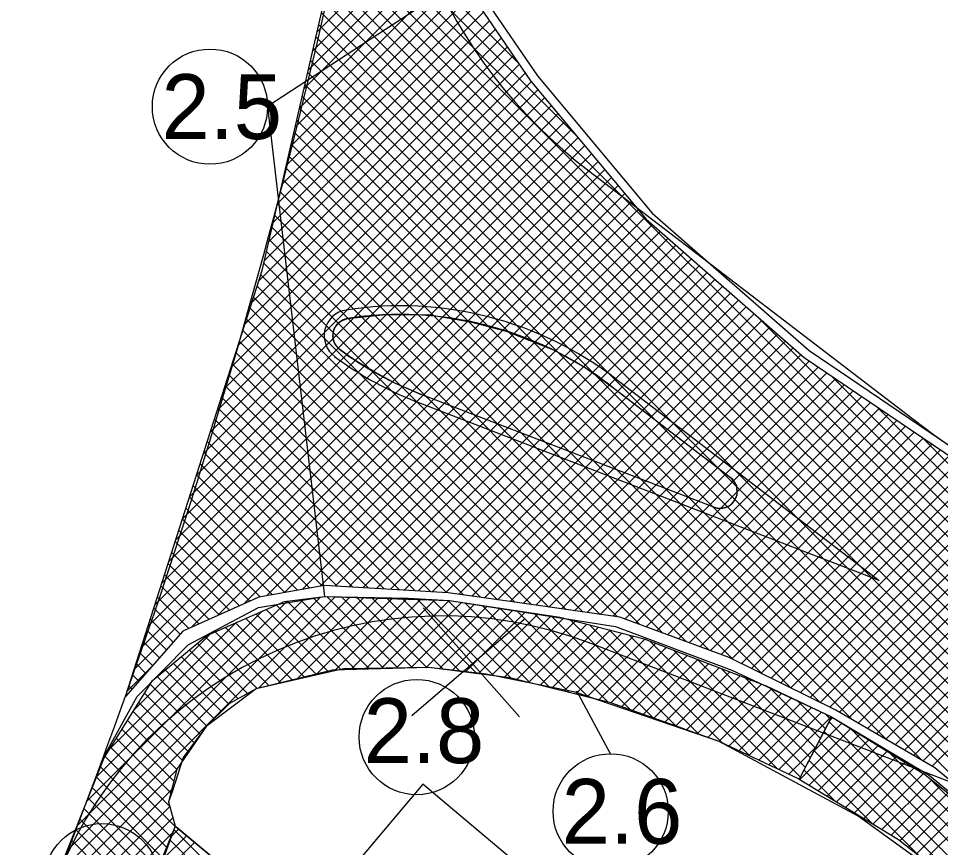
# Model space of a CAD drawing. Extents: x -438410 to -437811, y -1133174 to -1132817.
# Drawn here: x -438157.89 to -438131.22, y -1132954.3 to -1132930.32 of the extents above; entities that cross this region are included whole.
import ezdxf

# ---------------------------------------------------------------- set-up
doc = ezdxf.new("R2010")
doc.units = 0
for name, color, linetype in [('10 - legenda', 7, 'Continuous'), ('Vrstva 1', 7, 'Continuous'), ('Vrstva 5', 7, 'Continuous')]:
    doc.layers.add(name, color=color, linetype=linetype)

msp = doc.modelspace()

# ---------------------------------------------------------------- linework, layer by layer
at = {"layer": '10 - legenda'}
for p, q in [((-438148.336, -1132926.71), (-438143.442, -1132931.604)), ((-438148.415, -1132927.055), (-438141.759, -1132933.71)), ((-438149.256, -1132930.707), (-438145.83, -1132927.282)), ((-438148.495, -1132927.399), (-438113.459, -1132962.435)), ((-438149.383, -1132931.258), (-438145.694, -1132927.57)), ((-438148.574, -1132927.744), (-438113.683, -1132962.635)), ((-438149.509, -1132931.809), (-438145.558, -1132927.858)), ((-438149.636, -1132932.36), (-438145.422, -1132928.146)), ((-438148.653, -1132928.089), (-438113.907, -1132962.835)), ((-438149.763, -1132932.911), (-438145.286, -1132928.434)), ((-438148.733, -1132928.434), (-438114.132, -1132963.035)), ((-438149.89, -1132933.462), (-438145.15, -1132928.722)), ((-438148.812, -1132928.779), (-438114.356, -1132963.235)), ((-438150.017, -1132934.014), (-438145.014, -1132929.011)), ((-438150.143, -1132934.565), (-438144.878, -1132929.299)), ((-438148.891, -1132929.124), (-438114.58, -1132963.435)), ((-438150.27, -1132935.116), (-438144.741, -1132929.587)), ((-438148.971, -1132929.469), (-438114.805, -1132963.635)), ((-438150.397, -1132935.667), (-438144.605, -1132929.875)), ((-438149.05, -1132929.814), (-438115.029, -1132963.835)), ((-438150.524, -1132936.218), (-438144.447, -1132930.141)), ((-438150.651, -1132936.769), (-438144.274, -1132930.392)), ((-438149.129, -1132930.159), (-438115.253, -1132964.035)), ((-438150.778, -1132937.32), (-438144.101, -1132930.644)), ((-438149.209, -1132930.503), (-438115.478, -1132964.235)), ((-438150.94, -1132937.907), (-438143.928, -1132930.895)), ((-438149.288, -1132930.848), (-438115.702, -1132964.435)), ((-438151.14, -1132938.531), (-438143.756, -1132931.147)), ((-438149.368, -1132931.193), (-438115.926, -1132964.634)), ((-438151.341, -1132939.156), (-438143.583, -1132931.398)), ((-438151.541, -1132939.781), (-438143.41, -1132931.65)), ((-438149.447, -1132931.538), (-438116.151, -1132964.834)), ((-438151.742, -1132940.405), (-438143.237, -1132931.901)), ((-438149.526, -1132931.883), (-438116.375, -1132965.034)), ((-438151.942, -1132941.03), (-438143.063, -1132932.151)), ((-438149.606, -1132932.228), (-438116.599, -1132965.234)), ((-438152.142, -1132941.655), (-438142.87, -1132932.382)), ((-438152.343, -1132942.279), (-438142.676, -1132932.613)), ((-438149.685, -1132932.573), (-438116.824, -1132965.434)), ((-438152.744, -1132943.529), (-438142.29, -1132933.075)), ((-438152.543, -1132942.904), (-438142.483, -1132932.844)), ((-438149.764, -1132932.918), (-438117.048, -1132965.634)), ((-438152.944, -1132944.153), (-438142.097, -1132933.306)), ((-438149.844, -1132933.263), (-438129.751, -1132953.356)), ((-438153.144, -1132944.778), (-438141.904, -1132933.537)), ((-438149.923, -1132933.608), (-438131.752, -1132951.778)), ((-438153.345, -1132945.403), (-438141.711, -1132933.769)), ((-438153.545, -1132946.027), (-438141.518, -1132934)), ((-438150.003, -1132933.952), (-438132.768, -1132951.187)), ((-438153.746, -1132946.652), (-438141.324, -1132934.231)), ((-438150.082, -1132934.297), (-438133.783, -1132950.596)), ((-438153.946, -1132947.277), (-438141.131, -1132934.462)), ((-438150.161, -1132934.642), (-438134.704, -1132950.1)), ((-438154.347, -1132948.526), (-438140.745, -1132934.924)), ((-438154.147, -1132947.901), (-438140.938, -1132934.693)), ((-438154.547, -1132949.151), (-438140.552, -1132935.155)), ((-438150.241, -1132934.987), (-438135.542, -1132949.686)), ((-438152.903, -1132947.931), (-438140.359, -1132935.386)), ((-438150.32, -1132935.332), (-438136.38, -1132949.272)), ((-438152.139, -1132947.591), (-438140.166, -1132935.618)), ((-438150.399, -1132935.677), (-438137.218, -1132948.858)), ((-438151.375, -1132947.251), (-438139.972, -1132935.849)), ((-438150.479, -1132936.022), (-438137.912, -1132948.589)), ((-438150.717, -1132947.017), (-438139.779, -1132936.08)), ((-438150.2, -1132946.925), (-438139.56, -1132936.284)), ((-438150.558, -1132936.367), (-438138.583, -1132948.342)), ((-438149.683, -1132946.832), (-438139.333, -1132936.482)), ((-438150.638, -1132936.712), (-438139.253, -1132948.096)), ((-438149.167, -1132946.74), (-438139.107, -1132936.681)), ((-438150.717, -1132937.056), (-438139.924, -1132947.85)), ((-438148.738, -1132946.735), (-438138.881, -1132936.879)), ((-438148.337, -1132946.759), (-438138.655, -1132937.077)), ((-438147.936, -1132946.782), (-438138.429, -1132937.275)), ((-438150.796, -1132937.401), (-438140.57, -1132947.628)), ((-438147.535, -1132946.806), (-438138.202, -1132937.473)), ((-438150.885, -1132937.736), (-438141.065, -1132947.557)), ((-438147.135, -1132946.829), (-438137.976, -1132937.671)), ((-438146.734, -1132946.853), (-438137.75, -1132937.869)), ((-438150.988, -1132938.058), (-438141.56, -1132947.486)), ((-438146.333, -1132946.876), (-438137.524, -1132938.067)), ((-438151.092, -1132938.379), (-438142.055, -1132947.415)), ((-438145.932, -1132946.9), (-438137.298, -1132938.265)), ((-438145.531, -1132946.923), (-438137.071, -1132938.463)), ((-438145.155, -1132946.971), (-438136.845, -1132938.661)), ((-438151.195, -1132938.7), (-438142.55, -1132947.344)), ((-438144.784, -1132947.025), (-438136.619, -1132938.859)), ((-438136.551, -1132938.919), (-438113.234, -1132962.235)), ((-438151.298, -1132939.021), (-438143.045, -1132947.274)), ((-438144.413, -1132947.078), (-438136.393, -1132939.057)), ((-438151.401, -1132939.343), (-438143.541, -1132947.203)), ((-438144.042, -1132947.131), (-438136.167, -1132939.255)), ((-438143.671, -1132947.184), (-438135.94, -1132939.453)), ((-438151.504, -1132939.664), (-438144.036, -1132947.132)), ((-438143.3, -1132947.237), (-438135.714, -1132939.651)), ((-438151.607, -1132939.985), (-438144.531, -1132947.061)), ((-438142.929, -1132947.29), (-438135.488, -1132939.85)), ((-438142.558, -1132947.343), (-438135.262, -1132940.048)), ((-438142.186, -1132947.397), (-438135.019, -1132940.229)), ((-438151.71, -1132940.306), (-438145.026, -1132946.99)), ((-438141.815, -1132947.45), (-438134.766, -1132940.401)), ((-438151.813, -1132940.627), (-438145.516, -1132946.924)), ((-438141.444, -1132947.503), (-438134.513, -1132940.572)), ((-438141.073, -1132947.556), (-438134.261, -1132940.743)), ((-438134.389, -1132940.656), (-438113.01, -1132962.035)), ((-438151.916, -1132940.949), (-438145.967, -1132946.898)), ((-438140.702, -1132947.609), (-438134.008, -1132940.915)), ((-438140.359, -1132947.69), (-438133.755, -1132941.086)), ((-438152.019, -1132941.27), (-438146.418, -1132946.871)), ((-438140.048, -1132947.804), (-438133.502, -1132941.257)), ((-438152.122, -1132941.591), (-438146.868, -1132946.845)), ((-438139.738, -1132947.918), (-438133.249, -1132941.429)), ((-438139.428, -1132948.032), (-438132.996, -1132941.6)), ((-438133.074, -1132941.547), (-438112.786, -1132961.835)), ((-438139.117, -1132948.146), (-438132.743, -1132941.771)), ((-438152.225, -1132941.912), (-438147.319, -1132946.818)), ((-438138.807, -1132948.26), (-438132.49, -1132941.943)), ((-438138.497, -1132948.374), (-438132.237, -1132942.114)), ((-438152.328, -1132942.233), (-438147.77, -1132946.792)), ((-438138.187, -1132948.488), (-438131.984, -1132942.285)), ((-438152.431, -1132942.555), (-438148.22, -1132946.766)), ((-438137.876, -1132948.602), (-438131.731, -1132942.457)), ((-438137.566, -1132948.716), (-438131.478, -1132942.628)), ((-438131.759, -1132942.437), (-438112.561, -1132961.636)), ((-438152.534, -1132942.876), (-438148.671, -1132946.739)), ((-438137.262, -1132948.836), (-438131.225, -1132942.799)), ((-438152.637, -1132943.197), (-438149.105, -1132946.729)), ((-438136.978, -1132948.977), (-438130.972, -1132942.971)), ((-438136.694, -1132949.117), (-438130.707, -1132943.13)), ((-438136.41, -1132949.257), (-438130.42, -1132943.267)), ((-438136.126, -1132949.397), (-438130.133, -1132943.404)), ((-438152.74, -1132943.518), (-438149.465, -1132946.793)), ((-438135.842, -1132949.538), (-438129.846, -1132943.542)), ((-438135.558, -1132949.678), (-438129.56, -1132943.679)), ((-438152.843, -1132943.84), (-438149.825, -1132946.858)), ((-438135.274, -1132949.818), (-438129.273, -1132943.817)), ((-438134.99, -1132949.958), (-438128.986, -1132943.954)), ((-438152.946, -1132944.161), (-438150.185, -1132946.922)), ((-438134.706, -1132950.099), (-438128.699, -1132944.092)), ((-438134.422, -1132950.239), (-438128.412, -1132944.229)), ((-438153.049, -1132944.482), (-438150.545, -1132946.986)), ((-438134.145, -1132950.386), (-438128.126, -1132944.366)), ((-438133.876, -1132950.542), (-438127.839, -1132944.504)), ((-438153.153, -1132944.803), (-438150.905, -1132947.051)), ((-438133.608, -1132950.698), (-438127.552, -1132944.641)), ((-438133.34, -1132950.854), (-438127.265, -1132944.779)), ((-438133.072, -1132951.01), (-438126.978, -1132944.916)), ((-438132.804, -1132951.166), (-438126.691, -1132945.054)), ((-438153.256, -1132945.124), (-438151.205, -1132947.175)), ((-438132.536, -1132951.322), (-438126.405, -1132945.191)), ((-438132.268, -1132951.478), (-438126.096, -1132945.306)), ((-438153.359, -1132945.446), (-438151.498, -1132947.306)), ((-438131.999, -1132951.634), (-438125.774, -1132945.409)), ((-438131.731, -1132951.791), (-438125.452, -1132945.511)), ((-438131.463, -1132951.947), (-438125.13, -1132945.614)), ((-438153.462, -1132945.767), (-438151.792, -1132947.437)), ((-438153.565, -1132946.088), (-438152.085, -1132947.567)), ((-438153.668, -1132946.409), (-438152.379, -1132947.698)), ((-438153.771, -1132946.73), (-438152.673, -1132947.828)), ((-438156.76, -1132955.077), (-438148.729, -1132947.046)), ((-438156.479, -1132954.372), (-438149.161, -1132947.054)), ((-438156.197, -1132953.666), (-438149.642, -1132947.111)), ((-438155.916, -1132952.96), (-438150.124, -1132947.168)), ((-438153.874, -1132947.052), (-438152.966, -1132947.959)), ((-438150.947, -1132949.688), (-438148.312, -1132947.053)), ((-438150.398, -1132949.563), (-438147.895, -1132947.061)), ((-438150.125, -1132947.168), (-438148.167, -1132949.126)), ((-438149.848, -1132949.438), (-438147.479, -1132947.068)), ((-438149.746, -1132947.123), (-438147.749, -1132949.12)), ((-438149.366, -1132947.078), (-438147.331, -1132949.114)), ((-438149.299, -1132949.313), (-438147.062, -1132947.076)), ((-438148.979, -1132947.041), (-438146.913, -1132949.108)), ((-438148.75, -1132949.188), (-438146.645, -1132947.083)), ((-438148.547, -1132947.049), (-438146.494, -1132949.102)), ((-438148.265, -1132949.127), (-438146.243, -1132947.105)), ((-438148.115, -1132947.057), (-438146.076, -1132949.096)), ((-438147.834, -1132949.121), (-438145.841, -1132947.128)), ((-438147.683, -1132947.065), (-438145.6, -1132949.148)), ((-438147.404, -1132949.115), (-438145.44, -1132947.151)), ((-438147.251, -1132947.072), (-438145.115, -1132949.208)), ((-438146.973, -1132949.109), (-438145.07, -1132947.205)), ((-438146.819, -1132947.08), (-438144.63, -1132949.269)), ((-438146.377, -1132947.098), (-438144.145, -1132949.329)), ((-438145.927, -1132947.123), (-438143.657, -1132949.393)), ((-438145.477, -1132947.149), (-438143.093, -1132949.533)), ((-438144.984, -1132947.218), (-438142.529, -1132949.673)), ((-438155.635, -1132952.254), (-438150.833, -1132947.453)), ((-438153.977, -1132947.373), (-438153.22, -1132948.13)), ((-438150.733, -1132947.409), (-438148.916, -1132949.226)), ((-438150.438, -1132947.28), (-438148.57, -1132949.147)), ((-438146.543, -1132949.102), (-438144.701, -1132947.261)), ((-438146.185, -1132947.368), (-438143.406, -1132950.519)), ((-438146.113, -1132949.096), (-438144.333, -1132947.316)), ((-438145.724, -1132949.132), (-438143.964, -1132947.372)), ((-438145.347, -1132949.179), (-438143.595, -1132947.428)), ((-438144.97, -1132949.226), (-438143.227, -1132947.483)), ((-438144.484, -1132947.294), (-438141.964, -1132949.813)), ((-438143.984, -1132947.369), (-438141.4, -1132949.953)), ((-438143.485, -1132947.444), (-438140.836, -1132950.093)), ((-438154.08, -1132947.694), (-438153.418, -1132948.356)), ((-438151.323, -1132947.667), (-438149.607, -1132949.383)), ((-438151.028, -1132947.538), (-438149.261, -1132949.304)), ((-438146.513, -1132950.474), (-438143.271, -1132947.694)), ((-438144.593, -1132949.274), (-438142.858, -1132947.539)), ((-438144.216, -1132949.321), (-438142.489, -1132947.594)), ((-438143.838, -1132949.368), (-438142.13, -1132947.659)), ((-438143.483, -1132949.437), (-438141.793, -1132947.747)), ((-438142.985, -1132947.52), (-438140.188, -1132950.317)), ((-438142.486, -1132947.595), (-438139.527, -1132950.554)), ((-438141.95, -1132947.706), (-438138.866, -1132950.79)), ((-438155.258, -1132951.454), (-438151.588, -1132947.783)), ((-438154.183, -1132948.015), (-438153.616, -1132948.582)), ((-438151.913, -1132947.926), (-438150.298, -1132949.541)), ((-438151.618, -1132947.796), (-438149.953, -1132949.462)), ((-438143.143, -1132949.521), (-438141.457, -1132947.834)), ((-438142.803, -1132949.605), (-438141.12, -1132947.922)), ((-438142.463, -1132949.69), (-438140.783, -1132948.009)), ((-438141.377, -1132947.855), (-438138.205, -1132951.027)), ((-438140.804, -1132948.004), (-438137.526, -1132951.282)), ((-438154.545, -1132950.317), (-438152.342, -1132948.113)), ((-438152.491, -1132948.196), (-438150.989, -1132949.698)), ((-438152.208, -1132948.055), (-438150.644, -1132949.619)), ((-438142.123, -1132949.774), (-438140.446, -1132948.097)), ((-438141.783, -1132949.858), (-438140.109, -1132948.184)), ((-438141.443, -1132949.943), (-438139.775, -1132948.274)), ((-438140.231, -1132948.153), (-438136.728, -1132951.655)), ((-438154.286, -1132948.336), (-438153.815, -1132948.808)), ((-438152.722, -1132948.389), (-438151.268, -1132949.844)), ((-438141.103, -1132950.027), (-438139.468, -1132948.392)), ((-438140.764, -1132950.111), (-438139.162, -1132948.51)), ((-438139.629, -1132948.33), (-438135.93, -1132952.029)), ((-438154.389, -1132948.658), (-438154.013, -1132949.034)), ((-438153.184, -1132948.776), (-438151.809, -1132950.151)), ((-438152.953, -1132948.582), (-438151.54, -1132949.995)), ((-438140.451, -1132950.223), (-438138.855, -1132948.628)), ((-438140.138, -1132950.335), (-438138.549, -1132948.745)), ((-438138.94, -1132948.595), (-438135.282, -1132952.253)), ((-438154.748, -1132949.775), (-438154.056, -1132949.084)), ((-438154.492, -1132948.979), (-438154.211, -1132949.26)), ((-438153.415, -1132948.969), (-438152.021, -1132950.363)), ((-438139.826, -1132950.446), (-438138.243, -1132948.863)), ((-438139.514, -1132950.558), (-438137.936, -1132948.981)), ((-438138.251, -1132948.86), (-438135.137, -1132951.974)), ((-438154.595, -1132949.3), (-438154.409, -1132949.486)), ((-438153.878, -1132949.355), (-438152.446, -1132950.786)), ((-438153.647, -1132949.162), (-438152.234, -1132950.575)), ((-438139.201, -1132950.67), (-438137.63, -1132949.099)), ((-438138.889, -1132950.782), (-438137.323, -1132949.216)), ((-438138.576, -1132950.894), (-438137.017, -1132949.334)), ((-438137.562, -1132949.125), (-438134.992, -1132951.694)), ((-438154.698, -1132949.621), (-438154.607, -1132949.713)), ((-438154.081, -1132949.576), (-438152.623, -1132951.034)), ((-438138.264, -1132951.006), (-438136.71, -1132949.452)), ((-438137.952, -1132951.118), (-438136.404, -1132949.57)), ((-438136.873, -1132949.389), (-438134.847, -1132951.415)), ((-438154.244, -1132949.837), (-438152.796, -1132951.285)), ((-438137.639, -1132951.23), (-438136.107, -1132949.698)), ((-438137.35, -1132951.364), (-438135.819, -1132949.834)), ((-438136.169, -1132949.669), (-438134.702, -1132951.135)), ((-438154.408, -1132950.098), (-438152.97, -1132951.536)), ((-438137.061, -1132951.5), (-438135.532, -1132949.97)), ((-438136.772, -1132951.635), (-438135.244, -1132950.107)), ((-438135.364, -1132950.05), (-438134.558, -1132950.856)), ((-438154.571, -1132950.358), (-438153.144, -1132951.786)), ((-438136.483, -1132951.77), (-438134.956, -1132950.243)), ((-438136.194, -1132951.906), (-438134.668, -1132950.379)), ((-438154.735, -1132950.619), (-438153.315, -1132952.039)), ((-438135.905, -1132952.041), (-438134.383, -1132950.519)), ((-438134.558, -1132950.431), (-438134.413, -1132950.577)), ((-438134.449, -1132950.659), (-438120.721, -1132964.387)), ((-438134.429, -1132950.62), (-438134.352, -1132950.543)), ((-438154.898, -1132950.88), (-438153.401, -1132952.377)), ((-438135.291, -1132952.332), (-438133.828, -1132950.868)), ((-438134.892, -1132951.508), (-438134.09, -1132950.706)), ((-438134.594, -1132950.937), (-438120.304, -1132965.228)), ((-438133.795, -1132950.888), (-438121.138, -1132963.545)), ((-438155.062, -1132951.141), (-438153.487, -1132952.715)), ((-438135.028, -1132952.492), (-438133.566, -1132951.03)), ((-438134.764, -1132952.653), (-438133.304, -1132951.192)), ((-438134.74, -1132951.216), (-438119.886, -1132966.07)), ((-438155.225, -1132951.401), (-438153.516, -1132953.111)), ((-438135.616, -1132952.176), (-438134.839, -1132951.399)), ((-438134.5, -1132952.814), (-438133.041, -1132951.355)), ((-438155.389, -1132951.662), (-438153.364, -1132953.687)), ((-438134.885, -1132951.495), (-438131.82, -1132954.56)), ((-438134.237, -1132952.974), (-438132.779, -1132951.517)), ((-438133.973, -1132953.135), (-438132.517, -1132951.679)), ((-438132.681, -1132951.578), (-438121.555, -1132962.704)), ((-438155.517, -1132951.959), (-438153.487, -1132953.989)), ((-438135.031, -1132951.774), (-438133.195, -1132953.609)), ((-438133.71, -1132953.296), (-438132.255, -1132951.841)), ((-438133.446, -1132953.456), (-438131.993, -1132952.003)), ((-438157.042, -1132955.783), (-438153.321, -1132952.062)), ((-438155.638, -1132952.262), (-438153.61, -1132954.29)), ((-438135.327, -1132952.312), (-438135.295, -1132952.28)), ((-438135.176, -1132952.052), (-438134.282, -1132952.947)), ((-438133.183, -1132953.617), (-438131.731, -1132952.166)), ((-438132.919, -1132953.778), (-438131.49, -1132952.349)), ((-438132.655, -1132953.938), (-438131.254, -1132952.537)), ((-438131.471, -1132952.364), (-438122.863, -1132960.971)), ((-438157.323, -1132956.489), (-438153.466, -1132952.631)), ((-438155.759, -1132952.565), (-438153.732, -1132954.591)), ((-438132.397, -1132954.104), (-438131.017, -1132952.724)), ((-438155.88, -1132952.869), (-438153.855, -1132954.893)), ((-438132.16, -1132954.291), (-438130.781, -1132952.912)), ((-438157.605, -1132957.194), (-438153.517, -1132953.107)), ((-438156, -1132953.172), (-438153.978, -1132955.194)), ((-438131.923, -1132954.479), (-438130.544, -1132953.1)), ((-438131.686, -1132954.666), (-438130.308, -1132953.288)), ((-438157.886, -1132957.9), (-438153.427, -1132953.441)), ((-438156.121, -1132953.475), (-438154.101, -1132955.496)), ((-438157.605, -1132958.043), (-438153.443, -1132953.881)), ((-438156.242, -1132953.779), (-438154.224, -1132955.797)), ((-438153.461, -1132953.955), (-438153.268, -1132953.762)), ((-438153.395, -1132953.774), (-438135.149, -1132972.02)), ((-438156.363, -1132954.082), (-438154.347, -1132956.098)), ((-438153.949, -1132955.292), (-438152.805, -1132954.148)), ((-438153.705, -1132954.624), (-438153.036, -1132953.955)), ((-438153.509, -1132954.085), (-438135.343, -1132972.251))]:
    msp.add_line(p, q, dxfattribs=at)
for points in [[(-438130.381, -1132952.83), (-438131.389, -1132951.99), (-438134.253, -1132950.322), (-438137.334, -1132948.801), (-438140.501, -1132947.638), (-438143.534, -1132947.204), (-438145.467, -1132946.927), (-438149.041, -1132946.718), (-438150.937, -1132947.057), (-438153.137, -1132948.035), (-438154.797, -1132949.93), (-438150.843, -1132937.605), (-438147.876, -1132924.713)], [(-438146.757, -1132924.735), (-438144.335, -1132929.862), (-438142.882, -1132931.977), (-438139.562, -1132935.95), (-438135.02, -1132939.927), (-438130.686, -1132942.863), (-438127.863, -1132944.26), (-438126.21, -1132945.008), (-438124.099, -1132945.652), (-438123.021, -1132946.022), (-438119.29, -1132946.982), (-438116.055, -1132947.713), (-438110.044, -1132947.938), (-438105.196, -1132947.647), (-438095.924, -1132946.534)], [(-438146.983, -1132924.842), (-438144.552, -1132929.987), (-438143.081, -1132932.128), (-438139.741, -1132936.125), (-438135.173, -1132940.125), (-438130.812, -1132943.079), (-438127.97, -1132944.486), (-438126.298, -1132945.242), (-438124.176, -1132945.89), (-438123.093, -1132946.262), (-438119.349, -1132947.225), (-438116.088, -1132947.962), (-438110.041, -1132948.188), (-438105.174, -1132947.896), (-438095.894, -1132946.782)], [(-438144.552, -1132929.987), (-438143.081, -1132932.128), (-438139.741, -1132936.125), (-438135.173, -1132940.125), (-438130.812, -1132943.079)], [(-438157.894, -1132957.92), (-438155.415, -1132951.704), (-438154.014, -1132949.469), (-438152.448, -1132948.16), (-438150.203, -1132947.177), (-438149.044, -1132947.04), (-438146.626, -1132947.084), (-438145.423, -1132947.152), (-438142.231, -1132947.633), (-438139.799, -1132948.265), (-438136.269, -1132949.622), (-438134.381, -1132950.515), (-438135.315, -1132952.317), (-438137.63, -1132951.233), (-438140.758, -1132950.113), (-438143.68, -1132949.388), (-438146.02, -1132949.095), (-438148.497, -1132949.13), (-438151.016, -1132949.704), (-438151.793, -1132950.136), (-438152.461, -1132950.801), (-438153.313, -1132952.031), (-438153.553, -1132952.973), (-438153.362, -1132953.683), (-438155.504, -1132958.935)], [(-438155.418, -1132951.658), (-438154.459, -1132949.928), (-438152.986, -1132948.431), (-438150.952, -1132947.355), (-438149.044, -1132947.04), (-438145.423, -1132947.152), (-438140.626, -1132947.906), (-438137.256, -1132949.17), (-438134.381, -1132950.515), (-438131.551, -1132952.201), (-438128.583, -1132954.659), (-438124.25, -1132959.18), (-438121.599, -1132962.576), (-438119.849, -1132966.145), (-438117.528, -1132971.329), (-438116.418, -1132973.046), (-438114.656, -1132975.171), (-438090.957, -1132994.89), (-438086.882, -1132998.283), (-438085.153, -1132999.203), (-438076.272, -1133002.948), (-438073.404, -1133002.03)], [(-438128.583, -1132954.659), (-438131.681, -1132952.197), (-438134.379, -1132950.526), (-438135.315, -1132952.317), (-438132.442, -1132954.068), (-438129.905, -1132956.074)], [(-438129.69, -1132959.007), (-438131.441, -1132962.402), (-438134.136, -1132964.505), (-438136.029, -1132965.157), (-438137.396, -1132965.333), (-438139.278, -1132965.157), (-438141.329, -1132963.718), (-438153.362, -1132953.683), (-438154.448, -1132956.658), (-438144.574, -1132964.816), (-438142.244, -1132966.996), (-438141.125, -1132968.923), (-438139.739, -1132973.744)]]:
    msp.add_lwpolyline(points, dxfattribs=at)
for points in [[(-438148.378, -1132939), (-438147.357, -1132938.891), (-438146.044, -1132938.884), (-438144.822, -1132939.09), (-438143.784, -1132939.365), (-438142.418, -1132939.9), (-438141.501, -1132940.417), (-438140.712, -1132940.98), (-438139.641, -1132941.801), (-438137.298, -1132943.593), (-438137.124, -1132943.826), (-438137.117, -1132944.12), (-438137.229, -1132944.332), (-438137.328, -1132944.417), (-438137.475, -1132944.474), (-438137.657, -1132944.492), (-438137.782, -1132944.457), (-438146.244, -1132941.192), (-438146.984, -1132940.873), (-438147.587, -1132940.552), (-438148.107, -1132940.241), (-438148.345, -1132940.076), (-438148.599, -1132939.896), (-438148.721, -1132939.765), (-438148.78, -1132939.64), (-438148.8, -1132939.494), (-438148.766, -1132939.293), (-438148.669, -1132939.151), (-438148.571, -1132939.071)], [(-438153.362, -1132953.683), (-438141.329, -1132963.718), (-438139.289, -1132965.196), (-438137.396, -1132965.333), (-438135.25, -1132964.978), (-438134.136, -1132964.505), (-438132.444, -1132963.434), (-438131.441, -1132962.402), (-438130.504, -1132961.025), (-438129.696, -1132959.017), (-438129.592, -1132957.446), (-438129.905, -1132956.074), (-438133.603, -1132953.391), (-438137.63, -1132951.233), (-438141.796, -1132949.8), (-438144.368, -1132949.286), (-438146.02, -1132949.095), (-438148.81, -1132949.169), (-438151.016, -1132949.704), (-438152.461, -1132950.801), (-438153.127, -1132951.692), (-438153.435, -1132952.654), (-438153.553, -1132952.973)]]:
    msp.add_lwpolyline(points, close=True, dxfattribs=at)
for centre in [(-438152.355, -1132932.871), (-438146.374, -1132951.102), (-438140.765, -1132953.25), (-438155.482, -1132955.268)]:
    msp.add_circle(centre, 1.666, dxfattribs=at)
at = {"layer": 'Vrstva 1'}
for p, q in [((-438141.393, -1132934.729), (-438132.028, -1132941.897)), ((-438140.612, -1132940.742), (-438132.996, -1132946.572)), ((-438140.764, -1132940.94), (-438137.298, -1132943.593)), ((-438137.782, -1132944.457), (-438146.244, -1132941.192)), ((-438132.996, -1132946.572), (-438146.334, -1132941.425)), ((-438126.16, -1132954.25), (-438141.307, -1132948.405))]:
    msp.add_line(p, q, dxfattribs=at)
msp.add_lwpolyline([(-438146.195, -1132952.465), (-438149.086, -1132955.896), (-438140.7, -1132962.963), (-438137.833, -1132959.512)], close=True, dxfattribs=at)
for centre, radius, start, end in [((-438319.728, -1132891.239), 175.056, 338.61587, 350.60351), ((-438132.276, -1132922.818), 15, 173.6459, 232.5685), ((-438146.842, -1132948.881), 10.25, 52.5685, 98.8348), ((-438148.301, -1132939.494), 0.75, 98.8348, 233.4523), ((-438146.842, -1132948.881), 10, 52.5685, 98.8348), ((-438148.301, -1132939.494), 0.5, 98.8348, 233.4523), ((-438142.644, -1132931.862), 10, 233.4523, 248.8995), ((-438142.644, -1132931.862), 10.25, 233.4523, 248.8995), ((-438110.755, -1132914.104), 35, 232.5685, 308.9476), ((-438137.602, -1132943.99), 0.5, 248.8995, 52.5685), ((-438145.627, -1132959.601), 12, 68.8995, 157.9324)]:
    msp.add_arc(centre, radius, start, end, dxfattribs=at)
at = {"layer": 'Vrstva 5'}
msp.add_line((-438140.765, -1132951.585), (-438141.748, -1132949.776), dxfattribs=at)
msp.add_lwpolyline([(-438144.784, -1132929.003), (-438150.689, -1132932.871), (-438149.044, -1132947.04)], dxfattribs=at)

# ---------------------------------------------------------------- texts
for s, p in [('2.5', (-438153.756, -1132933.808)), ('2.8', (-438147.907, -1132951.855)), ('2.6', (-438142.179, -1132954.188))]:
    msp.add_text(s, height=1.875, dxfattribs=at).set_placement(p)

doc.saveas('drawing.dxf')
